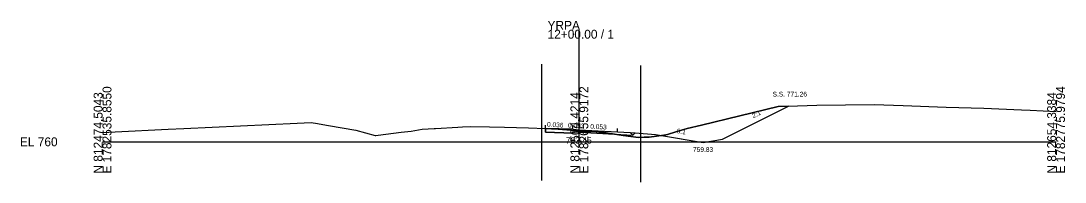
# Model space of a CAD drawing. Extents: x -26 to 2603, y -14 to 9545.
# Drawn here: x -25.7 to 302.8, y 1987.3 to 2038.1 of the extents above; entities that cross this region are included whole.
import ezdxf

# ---------------------------------------------------------------- set-up
doc = ezdxf.new("R2010")
doc.units = 0
for name, color, linetype in [('Exist Cross Section Cell', 7, 'Continuous'), ('Exist XS Center Line Elevation Label', 7, 'Continuous'), ('Exist XS Ground Line', 7, 'Continuous'), ('Prop XS Ditch Slope Text', 7, 'Continuous'), ('Prop XS Ditch Standard Text', 7, 'Continuous'), ('Prop XS Dump Level', 7, 'Continuous'), ('Prop XS Earthwork Shape', 7, 'Continuous'), ('Prop XS EOT Tick Mark', 7, 'Continuous'), ('Prop XS Exc Vertical Line 1', 7, 'Continuous'), ('Prop XS Exc Vertical Line 2', 7, 'Continuous'), ('Prop XS Finish Grade', 7, 'Continuous'), ('Prop XS Finish Grade Earthwork', 7, 'Continuous'), ('Prop XS Finish Grade Paved Shoulder', 7, 'Continuous'), ('Prop XS Finish Grade Pavement', 7, 'Continuous'), ('Prop XS Pvmt Edge Slope', 7, 'Continuous'), ('Prop XS SE Text', 7, 'Continuous'), ('Prop XS Side Slope Text', 7, 'Continuous'), ('Prop XS SS Elevation Text', 7, 'Continuous'), ('Prop XS Subgrade Earthwork', 7, 'Continuous'), ('Scratch_Level_6', 7, 'Continuous')]:
    doc.layers.add(name, color=color, linetype=linetype)

msp = doc.modelspace()

# ---------------------------------------------------------------- linework, layer by layer
at = {"layer": 'Exist Cross Section Cell'}
for p, q in [((150, 2000), (150, 2035.27)), ((0, 2000), (150, 2000)), ((150, 2000), (300, 2000))]:
    msp.add_line(p, q, dxfattribs=at)
at = {"layer": 'Exist XS Ground Line'}
for p, q in [((188.49, 2005.26), (212.55, 2011.15)), ((212.55, 2011.15), (224.71, 2011.54)), ((224.71, 2011.54), (242.72, 2011.76)), ((242.72, 2011.76), (251.84, 2011.45)), ((251.84, 2011.45), (265.44, 2010.94)), ((265.44, 2010.94), (277.29, 2010.56)), ((277.29, 2010.56), (289.12, 2010.06)), ((289.12, 2010.06), (291.8, 2009.96)), ((291.8, 2009.96), (300, 2009.59)), ((20.62, 2004), (25.62, 2004.22)), ((25.62, 2004.22), (61.27, 2005.84)), ((61.27, 2005.84), (65.64, 2006.05)), ((65.64, 2006.05), (66.24, 2006.02)), ((66.24, 2006.02), (66.97, 2005.89)), ((66.97, 2005.89), (71.06, 2005.17)), ((71.06, 2005.17), (79.65, 2003.64)), ((100.53, 2003.93), (104.29, 2004.16)), ((104.29, 2004.16), (104.75, 2004.2)), ((104.75, 2004.2), (111.8, 2004.66)), ((111.8, 2004.66), (113.25, 2004.72)), ((113.25, 2004.72), (115.81, 2004.83)), ((115.81, 2004.83), (121.74, 2004.71)), ((121.74, 2004.71), (126.48, 2004.6)), ((126.48, 2004.6), (133.98, 2004.39)), ((133.98, 2004.39), (139.37, 2004.24)), ((139.37, 2004.24), (141.27, 2004.13)), ((141.27, 2004.13), (143.35, 2004)), ((180.4, 2003.1), (183.9, 2004.2)), ((183.9, 2004.2), (188.49, 2005.26)), ((0, 2002.96), (3.97, 2003.16)), ((3.97, 2003.16), (20.62, 2004)), ((79.65, 2003.64), (85.73, 2001.99)), ((85.73, 2001.99), (86.03, 2002.04)), ((86.03, 2002.04), (86.72, 2002.11)), ((86.72, 2002.11), (93.99, 2003.01)), ((93.99, 2003.01), (97.13, 2003.38)), ((97.13, 2003.38), (100.53, 2003.93)), ((143.35, 2004), (150.18, 2003.43)), ((150.18, 2003.43), (150.66, 2003.4)), ((150.66, 2003.4), (151.15, 2003.39)), ((151.15, 2003.39), (155.31, 2003.22)), ((155.31, 2003.22), (157.77, 2002.95)), ((157.77, 2002.95), (161.09, 2002.44)), ((161.09, 2002.44), (163.79, 2002.02)), ((163.79, 2002.02), (165.33, 2001.74)), ((165.33, 2001.74), (168.61, 2001.36)), ((168.61, 2001.36), (170.4, 2001.48)), ((170.4, 2001.48), (172.02, 2001.5)), ((172.02, 2001.5), (174.24, 2001.76)), ((174.24, 2001.76), (177.18, 2002.22)), ((177.18, 2002.22), (177.72, 2002.33)), ((177.72, 2002.33), (180.4, 2003.1))]:
    msp.add_line(p, q, dxfattribs=at)
at = {"layer": 'Prop XS Dump Level'}
for p, q in [((148, 2003.93), (150, 2003.82)), ((150, 2003.82), (162, 2003.18))]:
    msp.add_line(p, q, dxfattribs=at)
at = {"layer": 'Prop XS Earthwork Shape'}
for points in [[(189, 1999.83), (195, 2000.83), (215.86, 2011.26), (212.55, 2011.15), (188.49, 2005.26), (183.9, 2004.2), (180.4, 2003.1), (177.72, 2002.33), (177.18, 2002.22), (175.88, 2002.02)], [(148, 2002.68), (148, 2003.14), (149.96, 2003.03), (161.12, 2002.44), (161.09, 2002.44), (157.77, 2002.95), (155.31, 2003.22), (151.15, 2003.39), (150.66, 2003.4), (150.18, 2003.43), (143.35, 2004), (141.27, 2004.13), (139.37, 2004.24), (139.35, 2004.24), (139.35, 2002.99)], [(167.55, 2002.84), (174, 2002.33), (175.88, 2002.02), (174.24, 2001.76), (172.02, 2001.5), (170.4, 2001.48), (168.61, 2001.36), (165.33, 2001.74), (163.79, 2002.02), (161.12, 2002.44), (166.84, 2002.13)]]:
    msp.add_lwpolyline(points, close=True, dxfattribs=at)
at = {"layer": 'Prop XS EOT Tick Mark'}
for p, q in [((139.35, 2004.24), (139.35, 2005.24)), ((148, 2003.93), (148, 2004.93)), ((162, 2003.18), (162, 2004.18))]:
    msp.add_line(p, q, dxfattribs=at)
at = {"layer": 'Prop XS Exc Vertical Line 1'}
msp.add_line((138.25, 1987.79), (138.25, 2024.48), dxfattribs=at)
at = {"layer": 'Prop XS Exc Vertical Line 2'}
msp.add_line((169.31, 1987.31), (169.31, 2024), dxfattribs=at)
at = {"layer": 'Prop XS Finish Grade'}
msp.add_line((166, 2002.97), (167.55, 2002.84), dxfattribs=at)
at = {"layer": 'Prop XS Finish Grade Earthwork'}
for p, q in [((195, 2000.83), (215.86, 2011.26)), ((167.55, 2002.84), (174, 2002.33)), ((174, 2002.33), (189, 1999.83)), ((189, 1999.83), (195, 2000.83))]:
    msp.add_line(p, q, dxfattribs=at)
at = {"layer": 'Prop XS Finish Grade Paved Shoulder'}
for p, q in [((148, 2003.93), (139.35, 2004.24)), ((162, 2003.18), (166, 2002.97))]:
    msp.add_line(p, q, dxfattribs=at)
at = {"layer": 'Prop XS Finish Grade Pavement'}
for p, q in [((148, 2003.93), (150, 2003.82)), ((150, 2003.82), (162, 2003.18))]:
    msp.add_line(p, q, dxfattribs=at)
at = {"layer": 'Prop XS Pvmt Edge Slope'}
msp.add_line((166, 2002.97), (166.84, 2002.13), dxfattribs=at)
at = {"layer": 'Prop XS Subgrade Earthwork'}
for p, q in [((139.35, 2002.99), (139.35, 2004.24)), ((148, 2002.68), (139.35, 2002.99)), ((148, 2003.14), (149.96, 2003.03)), ((148, 2002.68), (148, 2003.14)), ((149.96, 2003.03), (166.84, 2002.13)), ((166.84, 2002.13), (167.55, 2002.84))]:
    msp.add_line(p, q, dxfattribs=at)
at = {"layer": 'Scratch_Level_6'}
msp.add_lwpolyline([(148, 2002.68), (139.35, 2002.99), (139.35, 2004.24), (139.37, 2004.24), (141.27, 2004.13), (143.35, 2004), (150.18, 2003.43), (150.66, 2003.4), (151.15, 2003.39), (155.31, 2003.22), (157.77, 2002.95), (161.09, 2002.44), (161.12, 2002.44), (149.96, 2003.03), (148, 2003.14)], close=True, dxfattribs=at)

# ---------------------------------------------------------------- texts
at = {"layer": 'Exist Cross Section Cell'}
for s, p in [('YRPA', (140, 2035.27)), ('12+00.00 / 1', (140, 2032.47)), ('EL 760', (-26, 1998.6))]:
    msp.add_text(s, height=2.8, dxfattribs=at).set_placement(p)
for s, p in [('E 1782535.8550', (2.8, 1990)), ('E 1782655.9172', (152.8, 1990)), ('E 1782775.9794', (302.8, 1990)), ('N 812474.5043', (0, 1990)), ('N 812564.4214', (150, 1990)), ('N 812654.3384', (300, 1990))]:
    msp.add_text(s, height=2.8, rotation=90, dxfattribs=at).set_placement(p)
at = {"layer": 'Exist XS Center Line Elevation Label'}
msp.add_text('763.45', height=2, dxfattribs=at).set_placement((145.74, 1999.45))
at = {"layer": 'Prop XS Ditch Slope Text'}
msp.add_text('6:1', height=1.5, rotation=350.5377, dxfattribs=at).set_placement((180.55, 2002.76))
at = {"layer": 'Prop XS Ditch Standard Text'}
msp.add_text('759.83', height=1.5, dxfattribs=at).set_placement((185.77, 1996.83))
at = {"layer": 'Prop XS Dump Level'}
msp.add_text('Case4', height=0.04, dxfattribs=at).set_placement((174, 2002.29))
at = {"layer": 'Prop XS SE Text'}
for s, p in [('0.036', (139.81, 2004.76)), ('0.053', (146.41, 2004.51)), ('0.053', (153.41, 2004.14))]:
    msp.add_text(s, height=1.5, rotation=356.9456, dxfattribs=at).set_placement(p)
at = {"layer": 'Prop XS Side Slope Text'}
msp.add_text('2:1', height=1.5, rotation=26.5651, dxfattribs=at).set_placement((204.76, 2007.39))
at = {"layer": 'Prop XS SS Elevation Text'}
msp.add_text('S.S. 771.26', height=1.5, dxfattribs=at).set_placement((210.81, 2014.26))

doc.saveas('drawing.dxf')
